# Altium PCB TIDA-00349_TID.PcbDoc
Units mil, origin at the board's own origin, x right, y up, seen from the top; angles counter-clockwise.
Board outline 2200 x 1000 mil, 2 copper layers (Top Layer, Bottom Layer), stack 62 mil thick; 48 components, 20 nets, 93 pads, 4 vias.
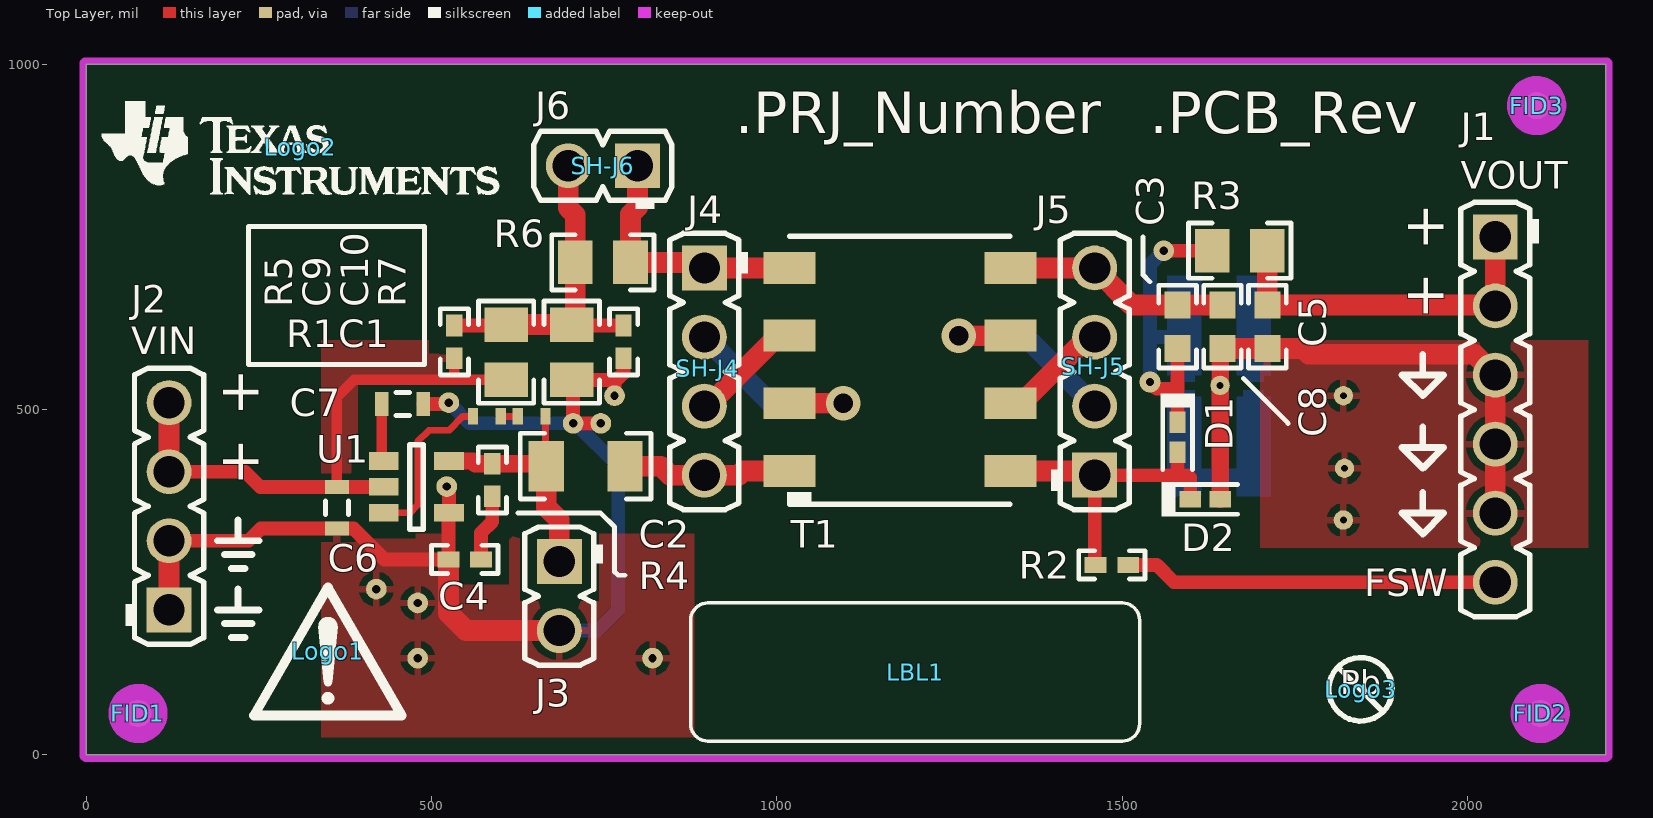
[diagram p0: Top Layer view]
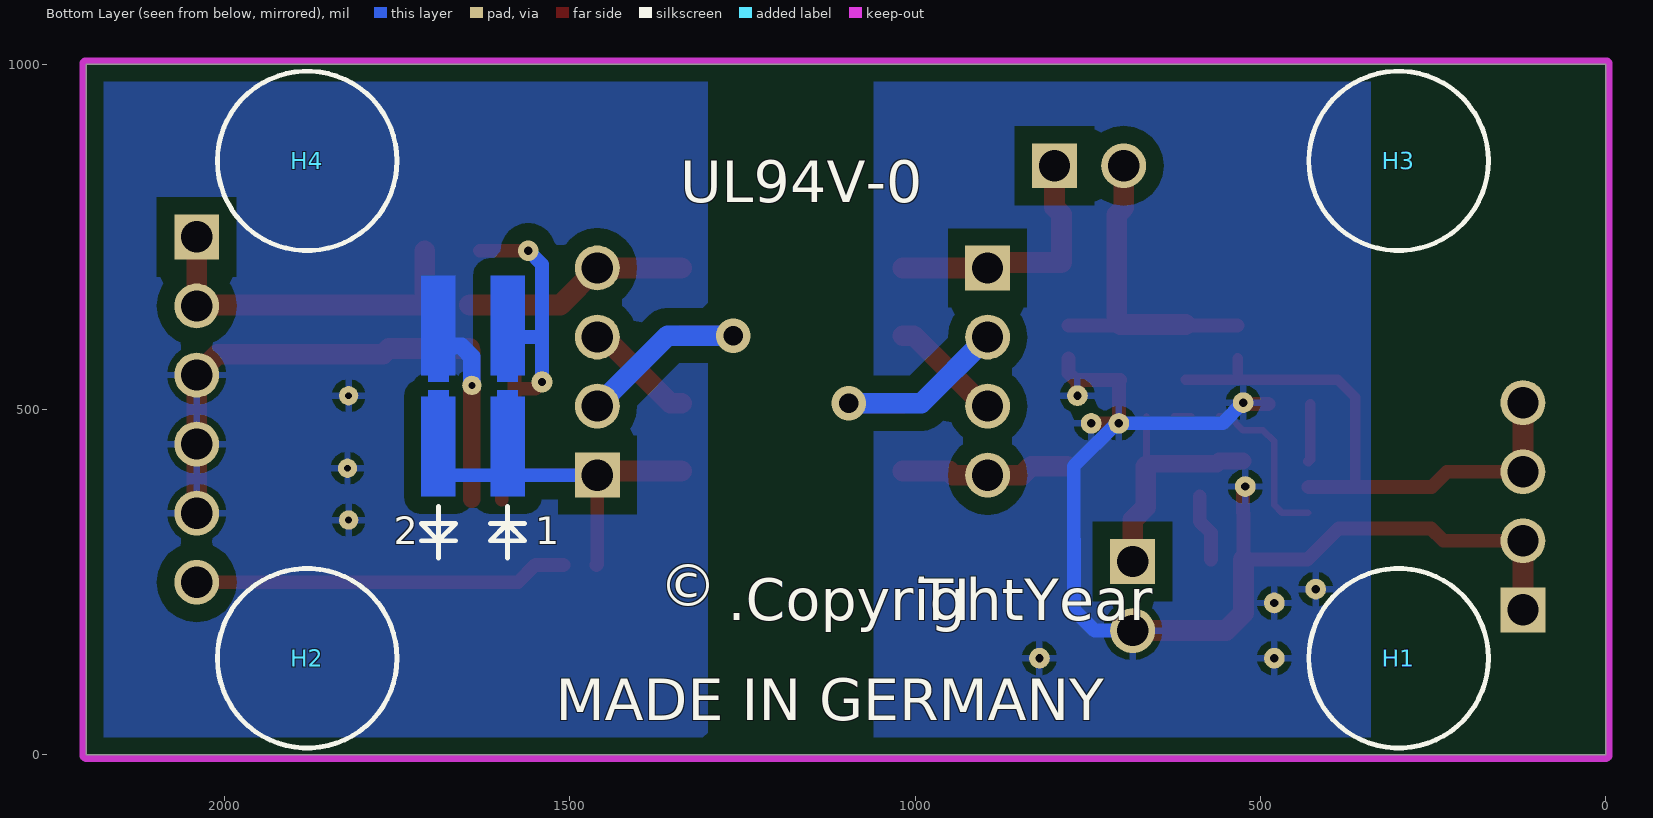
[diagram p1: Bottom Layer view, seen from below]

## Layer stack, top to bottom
Top Solder: solder mask 0.4, Solder Resist, Dk 3.5
Top Layer: signal copper 1.4
Dielectric1: core 59.2, FR-4, Dk 4.8
Bottom Layer: signal copper 1.4
Bottom Solder: solder mask 0.4, Solder Resist, Dk 3.5

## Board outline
0,0 2200,0 2200,1000 0,1000

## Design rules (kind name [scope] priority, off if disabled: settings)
AcuteAngle [All] p1: minimum=4.50000000000000E+0001 checktracksonly=FALSE
AssemblyTestPointUsage [All] p1: valid=2
Clearance Clearance_Keepouts [((IsTrack Or IsArc) And Not InPoly) And IsFree and IsKeepOut vs ((IsTrack Or IsArc) And Not InPoly) And IsFree and IsKeepOut] p1: gap=0
Clearance Clearance_BoardEdge_MountingHoles [OnCopper and InComponentClass('Mounting Holes') vs IsKeepOut] p2: gap=40
Clearance Clearance_BoardEdge_Poly [OnCopper and InPoly vs IsKeepOut] p3: gap=25
Clearance Clearance_BoardEdge [OnCopper and Not InComponentClass('Logo') and not InComponentClass('FiducialMark') and not InRegion(1000,500,4000,800) and Not IsKeepout vs IsKeepOut] p4: gap=75
Clearance Clearance_Poly [InPolygon] p5: gap=25
Clearance [All] p6: gap=7.87
ComponentClearance ComponentClearance_MountingHoles_FiducialMarks [InComponentClass('Mounting Holes') vs InComponentClass('FiducialMark')] p1: gap=50 collisioncheckmode=3 verticalgap=10 showdistances=FALSE
ComponentClearance ComponentClearance_Shunt [InComponentClass('Header') vs InComponentClass('Shunt')] p2: gap=0 collisioncheckmode=3 verticalgap=0 showdistances=FALSE
ComponentClearance ComponentClearance_Logo [InComponentClass('Logo')] p3: gap=50 collisioncheckmode=3 verticalgap=10 showdistances=FALSE
ComponentClearance ComponentClearance_ScrewToNut [(HasFootprint('NY PMS 440 0025 PH')) vs (HasFootprint('Keystone_1902C'))] p4: gap=5 collisioncheckmode=3 verticalgap=10 showdistances=FALSE
ComponentClearance ComponentClearance_MountingHoles [InComponentClass('Mounting Holes')] p5: gap=250 collisioncheckmode=3 verticalgap=100000 showdistances=FALSE
ComponentClearance ComponentClearance_SmallPassives [HasFootprint('0201*') or HasFootprint('0402*') or HasFootprint('0508') or HasFootprint('0603*') or HasFootprint('0612') or HasFootprint('0805*') or HasFootprint('0815*') or HasFootprint('0830*') or HasFootprint('1206*') or HasFootprint('1210*') or HasFootprint('1808*') or HasFootprint('1812*') or HasFootprint('1825*') or HasFootprint('2010*') or HasFootprint('2220*') or HasFootprint('2225*') or HasFootprint('2512*') or HasFootprint('2728*') or HasFootprint('3518*') vs HasFootprint('0201*') or HasFootprint('0402*') or HasFootprint('0508') or HasFootprint('0603*') or HasFootprint('0612') or HasFootprint('0805*') or HasFootprint('0815*') or HasFootprint('0830*') or HasFootprint('1206*') or HasFootprint('1210*') or HasFootprint('1808*') or HasFootprint('1812*') or HasFootprint('1825*') or HasFootprint('2010*') or HasFootprint('2220*') or HasFootprint('2225*') or HasFootprint('2512*') or HasFootprint('2728*') or HasFootprint('3518*')] p6: gap=20 collisioncheckmode=3 verticalgap=10 showdistances=FALSE
ComponentClearance ComponentClearance_THtoSMT [IsThruComponent vs IsSMTComponent] p7: gap=50 collisioncheckmode=3 verticalgap=30 showdistances=FALSE
ComponentClearance ComponentClearance_THtoTH [IsThruComponent vs IsThruComponent] p8: gap=50 collisioncheckmode=3 verticalgap=30 showdistances=FALSE
ComponentClearance [All] p9: gap=40 collisioncheckmode=3 verticalgap=10 showdistances=FALSE
DiffPairsRouting [All] p1: maxlimit=100 minlimit=10 mostfreqgap=10 toplayer_minwidth=15 toplayer_maxwidth=15 toplayer_prefwidth=15 bottomlayer_minwidth=15 bottomlayer_maxwidth=15 bottomlayer_prefwidth=15 maxuncoupledlength=1000
FabricationTestPointUsage TestPointUsage [All] p1: valid=2 allowmultiple=FALSE
FabricationTestpoint Testpoint [All] p1: side=3 testpointundercomponent=TRUE minsize=40 maxsize=100 preferedsize=60 minholesize=0 maxholesize=40 preferedholesize=32 testpointgrid=1 allowsidetop=TRUE allowsidebottom=TRUE usegrid=TRUE gridtolerance=0.01
FanoutControl Fanout_LCC [IsLCC] p1: bgadir=Out bgaviamode=Centered fanoutstyle=Auto fanoutdirection=Alternating viagrid=1 // Fanout_LCC (Default Rule)
FanoutControl Fanout_BGA [IsBGA] p2: bgadir=Out bgaviamode=Centered fanoutstyle=Auto fanoutdirection=Alternating viagrid=1 // Fanout_BGA (Default Rule)
FanoutControl Fanout_Default [All] p4: bgadir=Out bgaviamode=Centered fanoutstyle=Auto fanoutdirection=Alternating viagrid=1 // Fanout_Default (Default Rule)
FanoutControl Fanout_Small [(CompPinCount < 5)] p5: bgadir=Out bgaviamode=Centered fanoutstyle=Auto fanoutdirection=OutThenIn viagrid=1 // Fanout_Small (Default Rule)
HoleSize [All] p1: absolutevalues=TRUE maxlimit=251 minlimit=8 maxpercent=80.000 minpercent=20.000
MinimumAnnularRing MinimumAnnularRing_ThermalPadVias [IsVia and InAnyComponent] p1: minimumring=5.91
MinimumAnnularRing [All] p2: minimumring=9
MinimumSolderMaskSliver MinimumSolderMaskSliver_Logo [InComponentClass('Logo') vs InComponentClass('Logo')] p1: minsoldermaskwidth=0.7
MinimumSolderMaskSliver [All] p2: minsoldermaskwidth=3.94
PlaneConnect [All] p1: planeconnectstyle=Relief reliefexpansion=10 reliefentries=4 reliefconductorwidth=10 reliefairgap=10
PolygonConnect [All] p1: connectstyle=Relief reliefconductorwidth=10 reliefentries=4 polygonreliefangle="90 Angle" airgapwidth=10
RoutingVias ThermalPadVias [IsVia and InAnyComponent] p1: holewidth=7.87 width=19.68 viastyle="Through Hole" minholewidth=7.87 minwidth=19.68 maxholewidth=12.99 maxwidth=23.62
RoutingVias [All] p2: holewidth=16 width=34 viastyle="Through Hole" minholewidth=7.87 minwidth=26 maxholewidth=40 maxwidth=65
SilkToBoardRegionClearance [Not ((IsComment or IsDesignator) And (Hide <> 'False')) and not InRegion(1000,500,4000,800)] p1:
SilkToSilkClearance SilkToSilkClearance_Pb-FreeLogo [(HasFootprint('Pb-Free_Overlay_Medium') OR HasFootprint('Pb-Free_Overlay_Small')) vs (HasFootprint('Pb-Free_Overlay_Medium') OR HasFootprint('Pb-Free_Overlay_Small'))] p1: silktosilkclearance=0
SilkToSilkClearance [All] p2: silktosilkclearance=5
SilkToSolderMaskClearance "Silk to Solder Mask Opening" [All] p1: minsilkscreentomaskgap=1 clearancetoexposedcopper=FALSE
SolderMaskExpansion [All] p1: expansion=1.97
UnpouredPolygon [All] p1: allowunpoured=FALSE
Width [All] p1: maxlimit=100 minlimit=6 preferedwidth=10 checkconnectedcopper=TRUE
14 further rules are at their usual default settings.

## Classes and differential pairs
component class TIDA-00349_TID_Hardware: !PCB1 FID1 FID2 FID3 H1 H2 H3 H4 LBL1 Logo1 Logo2 Logo3 ZZ1 ZZ2 ZZ3 ZZ4 ZZ5 ZZ6 ZZ7
component class TIDA-00349_IsolatedDCDC: C1 C2 C3 C4 C5 C6 C7 C8 C9 C10 D1 D2 J1 J2 J3 J4 J5 J6 R1 R2 R3 R4 R5 R6 R7 SH-J4 SH-J5 SH-J6 T1 U1
component class Shunt: SH-J4 SH-J5 SH-J6
component class Header: J1 J2 J3 J4 J5 J6
component class FiducialMark: FID1 FID2 FID3
component class Logo: Logo2
component class AssemblyNote: ZZ1 ZZ2 ZZ3 ZZ4 ZZ5 ZZ6 ZZ7
component class Label: LBL1

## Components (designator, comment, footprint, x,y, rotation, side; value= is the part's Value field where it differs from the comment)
C1 "CAP, CERM, 1uF, 10V, +/-10%, X5R, 0402" 0402S 645,490 r0 top
C2 "CAP, CERM, 22uF, 10V, +/-10%, X5R, 1206" 1206 723.01,418 r180 top
C3 "CGB3B1X5R1A475K055AC" 0603 1580,620 r90 top
C4 "GRM155R71H561KA01D" 0402 548.01,283 r180 top
C5 "C1608X5R1E685K080AC" 0603 1710,620 r270 top
C6 "C0603C475K8PACTU" 0603S 363.01,358 r270 top
C7 "GRM188R71A105KA61D" 0603S 458.01,508 r0 top
C8 "CGB3B1X5R1A475K055AC" 0603 1645,620 r270 top
C9 "CAP, CERM, 10uF, 10V, +/-10%, X7R, 0805" 0805_HV 608.01,583 r90 top
C10 "CAP, CERM, 10uF, 10V, +/-10%, X7R, 0805" 0805_HV 703.01,583 r270 top
D1 "RB520S30,115" SOD-523 1580,460 r270 top
D2 "RB520S30,115" SOD-523 1620,370 r0 top
FID1 "Fiducial" Fiducial10-20 75,60 r0 top
FID2 "Fiducial" Fiducial10-20 2105,60 r0 top
FID3 "Fiducial" Fiducial10-20 2100,940 r0 top
H1 "SJ5382" 3M_SJ5382 300,140 r180 bottom
H2 "SJ5382" 3M_SJ5382 1880,140 r180 bottom
H3 "SJ5382" 3M_SJ5382 300,860 r180 bottom
H4 "SJ5382" 3M_SJ5382 1880,860 r180 bottom
J1 "61300611121" WURTH_61300611121 2040,500 r270 top
J2 "61300411121" WURTH_61300411121 120,360 r90 top
J3 "61300211121" WURTH_61300211121 685,230 r270 top
J4 "61300411121" WURTH_61300411121 895,555 r270 top
J5 "61300411121" WURTH_61300411121 1460,555 r90 top
J6 "61300211121" WURTH_61300211121 748.02,853 r180 top
LBL1 "Size: 0.65\" x 0.20 \"" Label_650x200 1200,120 r0 top
Logo1 "CAUTION.  READ USER GUIDE BEFORE USE" IEC_Caution_Small 350,150 r0 top
Logo2 "Texas Instruments" TI_Stacked_Overlay_Small_Vertical 310,880 r270 top
Logo3 "Pb-Free Symbol" Pb-Free_Overlay_Small 1845,95 r0 top
R1 "RES, 1.00k ohm, 1%, 0.063W, 0402" 0402S 580,490 r0 top
R2 "CRCW040210K0FKED" 0402 1485,275 r0 top
R3 "CRCW08050000Z0EAHP" 0805_HV 1670,730 r0 top
R4 "RES, 10.0 ohm, 1%, 0.063W, 0402" 0402 588.01,398 r90 top
R5 "RES, 499k ohm, 1%, 0.063W, 0402" 0402 533.01,598 r270 top
R6 "CRCW08050000Z0EAHP" 0805_HV 748.01,713 r180 top
R7 "RES, 499k ohm, 1%, 0.063W, 0402" 0402 778.01,598 r90 top
SH-J4 "969102-0000-DA" SNT-100-BK-G 900,560 r90 top
SH-J5 "969102-0000-DA" SNT-100-BK-G 1458.01,563 r90 top
SH-J6 "969102-0000-DA" SNT-100-BK-G 748.01,853 r180 top
T1 "750314839" Wurth_750314445 1178.01,558 r90 top
U1 "TPS60402DBV" DBV0005A_N 478.01,388 r0 top
ZZ1 "These assemblies are ESD sensitive, ESD precautions shall be observed." AssemblyNote 150,1975 r0 top
ZZ2 "These assemblies must be clean and free from flux and all contaminants. Use of no clean flux is not acceptable." AssemblyNote 150,1850 r0 top
ZZ3 "This Assembly Note is for PCB labels only" AssemblyNoteLabel 150,1725 r0 top
ZZ4 "These assemblies must comply with workmanship standards IPC-A-610 Class 2, unless otherwise specified." AssemblyNote 150,1600 r0 top
ZZ5 "Jumper/Shunt: SH-J4 on J4-PINs 2-3" AssemblyNote 150,1475 r0 top
ZZ6 "Jumper/Shunt: SH-J5 on J5-PINs 2-3" AssemblyNote 150,1350 r0 top
ZZ7 "Jumper/Shunt: SH-J6 on J6-PINs 1-2" AssemblyNote 150,1225 r0 top

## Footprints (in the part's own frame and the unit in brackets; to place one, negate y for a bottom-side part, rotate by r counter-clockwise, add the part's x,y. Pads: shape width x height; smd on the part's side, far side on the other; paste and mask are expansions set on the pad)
3M_SJ5382 [mil] "3M BUMPON"
  silkscreen extent -130,-130 130,130, body extent -124,-125 125,125, height 73
0402 [mm] "0402 from SM-752 data"
  rect 0.8x0.6 smd: 1(-0.6,0) 2(0.6,0)
  silkscreen extent -1.22,-0.52 1.22,0.52, body extent -0.55,-0.3 0.55,0.3, height 0.6
0402S [mil] "Based on C0402S footprint from PADS legacy"
  rect 15x24 smd: 1(-20,0) 2(20,0)
  body extent -22,-12 22,12, height 24
0603 [mm] "0603 from SM-752 data"
  rect 1x0.95 smd: 1(-0.8,0) 2(0.8,0)
  silkscreen extent -1.52,-0.69 1.52,0.69, body extent -0.87,-0.47 0.87,0.47, height 0.85
0603S [mil]
  rect 20x35 smd: 1(-30,0) 2(30,0)
  silkscreen extent -10,-17 10,17, body extent -34,-19 34,19, height 33
0805_HV [mil] "0805 with 30mil clearance between pads"
  rect 50x63 smd: 1(-40,0) 2(40,0)
  silkscreen extent -74,-40 74,40, body extent -43,-29 43,29, height 43
1206 [mm] "1206 from SM-752 data"
  rect 1.3x1.85 smd: 1(-1.45,0) 2(1.45,0)
  silkscreen extent -2.4,-1.21 2.4,1.21, body extent -1.7,-0.9 1.7,0.9, height 1.35
AssemblyNote [mil] "Assembly Note"
AssemblyNoteLabel [mil] "Assembly Note for PCB Labels"
DBV0005A_N [mm] "SOT23, 5-Leads, Body 2.9x1.6mm, Pitch 0.95mm, Lead Span 2.8mm, IPC Medium Density"
  rect 1.1x0.65 smd: 1(-1.2,0.95) 2(-1.2,0) 3(-1.2,-0.95) 4(1.2,-0.95) 5(1.2,0.95)
  silkscreen extent -0.25,-1.55 0.25,1.55, body extent -1.42,-1.46 1.42,1.46, height 1.08
Fiducial10-20 [mm]
  round 1 smd mask+0.5: 1(0,0)
  Top Layer keep-out circle w1.178: c0,0 r0.5
IEC_Caution_Small [mil]
  silkscreen extent -107,-93 107,92
Label_650x200 [mil] "Thermal Transfer Label"
  round 1 on Mech13: 0(0,0)
  silkscreen extent -325,-100 325,100, body extent -326,-101 326,101, height 1
Pb-Free_Overlay_Small [mil]
  silkscreen extent -46,-46 46,46
SNT-100-BK-G [mil] "Samtec STEP model"
  round 1 on Mech3: 0(0,0)
  body extent -100,-50 100,50, height 344
SOD-523 [mm] "NXP Semiconductor recommended land pattern, nominal STEP model"
  rect 0.8x0.6 smd paste-0.05: 1(-0.55,0) 2(0.55,0)
  silkscreen extent -1.6,-0.64 1.2,0.63, body extent -0.8,-0.4 0.8,0.4, height 0.72
TI_Stacked_Overlay_Small_Vertical [mil]
  silkscreen extent -66,-288 69,288
Wurth_750314445 [mm] "WURTH"
  rect 1.17x1.91 smd: 1(-3.735,4.065) 2(-1.245,4.065) 3(1.245,4.065) 4(3.735,4.065) 5(3.735,-4.065) 6(1.245,-4.065) 7(-1.245,-4.065) 8(-3.735,-4.065)
  silkscreen extent -5,-4.05 4.9,4.15, body extent -4.92,-4.58 4.9,4.58, height 10.1
WURTH_61300211121 [mm] "Header, 2.54mm, 2x1, TH"
  rect 1.65x1.65 hole 1.15: 1(-1.27,0)
  round 1.65 hole 1.15: 2(1.27,0)
  silkscreen extent -2.54,-1.27 2.54,1.6, body extent -2.54,-1.27 2.54,1.27, height 8.54
WURTH_61300411121 [mm] "Header, 2.54mm, 4x1, TH"
  rect 1.65x1.65 hole 1.15: 1(-3.81,0)
  round 1.65 hole 1.15: 2(-1.27,0) 3(1.27,0) 4(3.81,0)
  silkscreen extent -5.08,-1.27 5.08,1.6, body extent -5.08,-1.27 5.08,1.27, height 8.54
WURTH_61300611121 [mm] "Header, 2.54mm, 6x1, TH"
  rect 1.65x1.65 hole 1.15: 1(-6.35,0)
  round 1.65 hole 1.15: 2(-3.81,0) 3(-1.27,0) 4(1.27,0) 5(3.81,0) 6(6.35,0)
  silkscreen extent -7.62,-1.27 7.62,1.6, body extent -7.62,-1.27 7.62,1.27, height 8.54

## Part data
C1: library part GRM155R61A105KE15D
C2: library part GRM31CR61A226KE19L
C3 C8: "CAP, CERM, 4.7 µF, 10 V, +/- 10%, X5R, 0603"
C4: "CAP, CERM, 560pF, 50V, +/-10%, X7R, 0402"
C5: "CAP, CERM, 6.8 µF, 25 V, +/- 10%, X5R, 0603"
C6: "CAP, CERM, 4.7uF, 10V, +/-10%, X5R, 0603"
C7: "CAP, CERM, 1uF, 10V, +/-10%, X7R, 0603"
C9 C10: library part GRM21BR71A106KE51L
D1 D2: "Diode, Schottky, 30 V, 0.2 A, SOD-523"
FID1 FID2 FID3: "Fiducial mark.  There is nothing to buy or mount."
H1 H2 H3 H4: "Bumpon, Hemisphere, 0.25 X 0.075, Clear"
J1: "Header, 2.54 mm, 6x1, Gold, TH"
J2 J4 J5: "Header, 2.54 mm, 4x1, Gold, TH"
J3 J6: "Header, 2.54 mm, 2x1, Gold, TH"
LBL1: library part THT-14-423-10, "Thermal Transfer Printable Labels, 0.650\" W x 0.200\" H - 10,000 per roll"
Logo1: library part IEC_Caution, "IEC 61010-1 Caution Warning"
Logo2: library part TI_Logo, "Texas Instrument Corporate Signature"
Logo3: library part Pb-Free
R1: library part CRCW04021K00FKED
R2: "RES, 10.0 k, 1%, 0.063 W, 0402"
R3 R6: "RES, 0, 5%, 0.333 W, 0805"
R4: library part CRCW040210R0FKED
R5 R7: library part CRCW0402499KFKED
SH-J4 SH-J5 SH-J6: "Shunt, 100mil, Gold plated, Black"
T1: "Transformer, 3mH, SMT"
U1: "UNREGULATED 60-mA CHARGE PUMP VOLTAGE INVERTER, DBV0005A"
ZZ1 ZZ2 ZZ4 ZZ5 ZZ6 ZZ7: library part AssemblyNote
ZZ3: library part AssemblyNoteLabel

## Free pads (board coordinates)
  round 30 hole 12: 0(420,240) 0(480,140) 0(480,220) 0(522,388.55) 0(525,510) 0(705,480) 0(745,480) 0(765,520) 0(820,140)
  round 28 hole 10: 0(1641.65,535) 0(1820,340) 0(1820,520) 0(1821.65,415)

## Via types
v1: diameter 30, hole 12, Top Layer to Bottom Layer, 2 vias
v2: diameter 50, hole 28, Top Layer to Bottom Layer, 2 vias

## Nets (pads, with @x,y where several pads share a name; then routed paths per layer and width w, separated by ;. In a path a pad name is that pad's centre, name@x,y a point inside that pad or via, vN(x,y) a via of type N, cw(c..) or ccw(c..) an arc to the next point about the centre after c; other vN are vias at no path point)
GND: C4.2 C6.2 C7.2 C10.2 J2.1 J2.2 J3.2 pad.0@420,240 pad.0@480,140 pad.0@480,220 pad.0@522,388.55 pad.0@525,510 pad.0@705,480 pad.0@745,480 pad.0@765,520 pad.0@820,140 R7.1 U1.4 | length 1737.4
  Top Layer w20: J2.2 235,310 253,328 C6.2 387,328 432,283 C4.2 U1.4@524.39,349.73 ; C7.2 pad.0@523,508 ; pad.0@522,388.55 525.26,385.29 U1.4 ; pad.0@745,480 705,480 705,541.01 C10.2 768,543 ; pad.0@765,520 765,540 768,543 ; R7.1 778.01,553.01 768,543
  Top Layer w30: J2.1 J2.2 ; C4.2 524.39,205.61 550,180 J3.2
  Bottom Layer w20: pad.0@525,510 554.91,480.09 705,480 708.24,480 770.24,418 770,210 740,180 J3.2
ISOGND: C5.2 C8.2 D2.2 J1.3 J1.4 J1.5 pad.0@1641.65,535 pad.0@1820,340 pad.0@1820,520 pad.0@1821.65,415 | length 928.5
  Top Layer w25: D2.2 1641.65,535 1641.65,585.16 C8.2
  Top Layer w30: C8.2 C5.2 1761.5,588.5 1770,580 2010,580 J1.3 J1.4 J1.5
  Bottom Layer w25: pad.0@1641.65,535 1641.65,576.65 1656.95,591.95 1691.32,591.95
NetC1_1: C1.1 R1.2 | length 25
  Top Layer w10: R1.2 C1.1
NetC1_2: C1.2 C2.2 J3.1 R4.2 U1.5 | length 360.7
  Top Layer w10: C1.2 665,418.93 C2.2
  Top Layer w25: U1.5 559.6,425.4 563.38,421.62 R4.2 662.3,421.62 C2.2@665,418.93
  Top Layer w30: C2.2 665.93,359.07 685,340 J3.1
NetC2_1: C2.1 J4.4 T1.1 | length 245.7
  Top Layer w30: C2.1 832,418 845,405 J4.4 945,405 950.95,410.95 T1.1
NetC3_1: C3.1 D1.1 R3.1 | length 464.3
  Top Layer w20: v1(1540,540) 1550,530 1580,530 ; v1(1560,730) R3.1 ; D1.1 1580,530 ; C3.1 1580,530
  Bottom Layer w20: v1(1540,540) 1540,605 ; v1(1560,730) 1540,710 1540,605 ; 1585,605 1540,605
NetC3_2: C3.2 C8.1 J5.4 T1.5 | length 329.1
  Top Layer w30: T1.5 T1.5 J5.4 1513.5,651.5 C3.2 C8.1
NetC4_1: C4.1 R4.1 | length 98.2
  Top Layer w20: C4.1 571.63,321.63 588.01,338.01 R4.1
NetC5_1: C5.1 J1.1 J1.2 R3.2 | length 506.1
  Top Layer w30: R3.2 C5.1 2038.5,651.5 2040,652.99 J1.1
NetC7_1: C7.1 U1.1 | length 83.7
  Top Layer w15: C7.1 428.01,428.16 U1.1
NetC9_2: C9.2 C10.1 J6.2 R5.1 R6.2 R7.2 | length 482.4
  Top Layer w20: R5.1 606.63,621.62 C9.2 ; C10.1 704.39,621.62 R7.2
  Top Layer w30: C9.2 C10.1 708.01,628 R6.2 708.01,781.99 698.02,791.98 J6.2
NetD1_2: D1.2 D2.1 J5.1 R2.1 T1.8 | length 689.7
  Top Layer w20: R2.1 1460,276.38 J5.1 1580,405 ; D1.2 1580,405 ; D2.1 1598.35,401.65 1595,405 1580,405
  Top Layer w30: T1.8 1454.05,410.95 J5.1
  Bottom Layer w20: J5.1 1690,405
NetJ1_6: J1.6 R2.2 | length 541.7
  Top Layer w20: R2.2 1550,275 1575,250 J1.6
NetJ4_1: J4.1 J6.1 R6.1 T1.4 | length 377.4
  Top Layer w30: J6.1 798.02,792.77 788.01,782.77 R6.1 887,713 J4.1 1017.93,705 T1.4
NetJ4_2: J4.2 T1.2 | length 318.8
  Top Layer w30: T1.2 v2(1096.02,508.98)
  Bottom Layer w30: J4.2 991.02,508.98 v2(1096.02,508.98)
NetJ4_3: J4.3 T1.3 | length 165.2
  Top Layer w30: J4.3 900,505 1002.02,607.02 T1.3
NetJ5_2: J5.2 T1.6 | length 324.3
  Top Layer w20: J5.2@1468.01,508 J5.2@1468.01,518
  Top Layer w30: v2(1262.98,607.02) T1.6
  Bottom Layer w30: v2(1262.98,607.02) 1357.98,607.02 J5.2
NetJ5_3: J5.3 T1.7 | length 161.7
  Top Layer w30: T1.7 1354.14,508.98 1450.16,605 J5.3
NetR1_1: R1.1 U1.3 | length 240.9
  Top Layer w10: U1.3 468.77,350.6 480,361.83 480,453.87 496.13,470 525,470 545,490 R1.1
VIN: C6.1 C9.1 J2.3 J2.4 R5.2 U1.2 | length 837.9
  Top Layer w15: C6.1 363.01,518.01 388,543 530,543 ; R5.2 533.01,546.01 530,543 ; C9.1 530,543
  Top Layer w20: J2.3 230,410 252,388 C6.1 U1.2
  Top Layer w30: J2.3 J2.4
pads on no net: FID1.1 FID2.1 FID3.1 LBL1.0 SH-J4.0 SH-J5.0 SH-J6.0

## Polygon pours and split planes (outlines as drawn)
GND on Bottom Layer "Bottom Layer-No Net 1" (solid, remove dead copper, pour order 10): 340,0 340,1000 1060,1000 1060,0
ISOGND on Bottom Layer "Bottom Layer-No Net" (solid, remove dead copper, pour order 2): 2200,1000 1300,1000 1300,0 2200,0
ISOGND on Top Layer "Top Layer-No Net 2" (solid, remove dead copper, pour order 12): 1700,560 1700,300 2200,300 2200,600 1700,600
VIN on Top Layer "Top Layer-No Net 1" (solid, remove dead copper, pour order 8): 340,400 340,600 540,600 540,400
GND on Top Layer "Top Layer-No Net" (solid, remove dead copper, pour order 6): 340,320 340,0 880,0 880,320

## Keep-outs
Keep-Out Layer:
  lines w10: -5,0 ccw(c0,0) 0,-5 ; -5,0 ccw(c0,0) 0,-5 ; -5,0 -5,1000 ; -5,1000 cw(c0,1000) 0,1005 ; -5,1000 cw(c0,1000) 0,1005 ; 0,-5 2200,-5 ; 0,1005 2200,1005 ; 2200,-5 ccw(c2200,0) 2205,0 ; 2200,-5 ccw(c2200,0) 2205,0 ; 2200,1005 cw(c2200,1000) 2205,1000 ; 2200,1005 cw(c2200,1000) 2205,1000 ; 2205,0 2205,1000
  text ".Layer_Name" at 577,-858.49 h60

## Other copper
Top Layer:
  text ".Layer_Name" at 577,-858.49 h60
Bottom Layer:
  rectangle net NetC3_1: 1575,540 1605,549
  rectangle net NetD1_2: 1575,519 1605,528
  rectangle net NetD1_2: 1675,519 1705,528
  rectangle net ISOGND: 1675,540 1705,549
  rectangle net ISOGND: 1665,549 1715,694
  rectangle net NetD1_2: 1665,374 1715,519
  rectangle net NetD1_2: 1565,374 1615,519
  rectangle net NetC3_1: 1565,549 1615,694
  text ".Layer_Name" at 577,-858.49 h60

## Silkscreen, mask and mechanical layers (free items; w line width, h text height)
Top Overlay:
  lines w7: 625,350 745,350 765,330 765,265 770,260 780,260 ; 1530,750 1530,695 1540,685 ; 1675,545 1740,480 ; 235,565 235,765 490,765 490,565 235,565
  lines w10: 190,210 250,210 ; 190,310 250,310 ; 200,190 240,190 ; 200,290 240,290 ; 210,170 230,170 ; 210,270 230,270 ; 220,210 220,240 ; 220,310 220,340 ; 1935,350 1935,380 ; 1935,445 1935,475 ; 1935,550 1935,580 ; 1905,350 1965,350 1935,320 1905,350 ; 1905,445 1965,445 1935,415 1905,445 ; 1905,550 1935,520 1965,550 1905,550
  text ".PRJ_Number" at 940,900 h60
  text ".PCB_Rev" at 1540,900 h60
  text "VOUT" at 1990,820 h40
  text "+" at 1965,730 h60 r90
  text "+" at 1965,630 h60 r90
  text "VIN" at 65,580 h40
  text "+" at 250,490 h60 r90
  text "+" at 250,390 h60 r90
  text "FSW" at 1850,230 h40
  text ".Layer_Name" at 577,-858.49 h60
Bottom Overlay:
  lines w7: 1565,335 1615,335 ; 1590,285 1590,360 ; 1665,310 1715,310 ; 1690,285 1690,360 ; 1565,310 1590,335 1615,310 1565,310 ; 1665,335 1690,310 1715,335 1665,335
  text "UL94V-0" at 1340,800 h60
  text "1" at 1550,305 h40
  text "2" at 1755,305 h40
  text "TI" at 995,195 h60
  text ".CopyrightYear" at 1271,195 h60
  text "©" at 1370,195 h105
  text "MADE IN GERMANY" at 1520,50 h60
  text ".Layer_Name" at 577,-858.49 h60
Top Paste:
  text ".Layer_Name" at 577,-858.49 h60
Bottom Paste:
  text ".Layer_Name" at 577,-858.49 h60
Top Solder:
  text ".Layer_Name" at 577,-858.49 h60
  text ".Layer_Name" at 577,-858.49 h60
Bottom Solder:
  text ".Layer_Name" at 577,-858.49 h60
Drill Guide:
  text ".Layer_Name" at 577,-858.49 h60
M1 Board Outline:
  the board outline again, w10
  text ".Layer_Name" at 577,-858.49 h60
M2 Board Dimensions:
  rectangle: 125,-400 500,-275
  rectangle: 0,-275 125,-150
  lines w7: 0,-275 1000,-275 ; 125,-400 125,-150 ; 250,-400 250,-150 ; 500,-400 500,-150 ; 750,-400 750,-150 ; 0,-400 0,-150 1000,-150 1000,-400 0,-400
  text ".Layer_Name" at 577,-858.49 h60
M3 3D STEP Top:
  text ".Layer_Name" at 577,-858.49 h60
M4 3D STEP Bottom:
  text ".Layer_Name" at 577,-858.49 h60
M5 Assembly Top:
  lines w10: -292,-930.17 6308,-930.17 ; -292,-726.83 6310,-726.83 ; -292,-523.5 -292,-1133.5 3713,-1133.5 6310,-1133.5 6310,-523.5 -291.5,-523.5 -291.5,-1133.5 1284,-1133.5 ; 2173,-1133.5 2173,-523.5 ; 3440,-726.83 3440,-523.5 ; 4280,-726.83 4280,-523.5 ; 4902,-1140 4902,-937.17
  text "COMPONENTS MARKED 'DNP' SHOULD NOT BE POPULATED." at 1153.5,-318.5 h60
  text "ASSEMBLY VARIANT:" at 1153,-434 h60
  text ".VariantName" at 2189,-434 h60
  text "PCB VIEWED FROM TOP SIDE" at -228.5,-655.67 h60
  text "BOARD #:" at 2248,-655.67 h60
  text ".PRJ_Number" at 2793.5,-655.67 h60
  text "REV:" at 3638,-655.67 h60
  text ".PCB_Rev" at 3929.5,-655.67 h60
  text "SVN REV:" at 4476,-655.67 h60
  text ".VersionControl_RevNumber" at 4982,-655.67 h60
  text "PLOT NAME =" at -228.5,-1064.34 h60
  text ".plot_File_Name" at 577,-1064.34 h60
  text "GENERATED    :" at 2250,-1064.34 h60
  text ".Print_Date" at 3119.5,-1064.34 h60
  text ".Print_Time" at 3848.5,-1064.34 h60
  text "TEXAS INSTRUMENTS" at 5113,-1064.34 h60
M6 Assembly Bottom:
  lines w10: -292.5,-727.33 6309.5,-727.33 ; -290.5,-930.67 6309.5,-930.67 ; 1115.5,-1140.5 1115.5,-937.67 ; 1737.5,-727.33 1737.5,-524 ; 2577.5,-727.33 2577.5,-524 ; 3844.5,-1134 3844.5,-524 ; 4733.5,-1134 6309,-1134 6309,-524 -292.5,-524 -292.5,-1134 2304.5,-1134 6309.5,-1134 6309.5,-524
  text "COMPONENTS MARKED 'DNP' SHOULD NOT BE POPULATED." at 6102,-318 h60
  text ".VariantName" at 5058,-434 h60
  text "ASSEMBLY VARIANT:" at 6097,-434 h60
  text ".VersionControl_RevNumber" at 1035.5,-656.17 h60
  text "SVN REV:" at 1541.5,-656.17 h60
  text ".PCB_Rev" at 2088,-656.17 h60
  text "REV:" at 2379.5,-656.17 h60
  text ".PRJ_Number" at 3224,-656.17 h60
  text "BOARD #:" at 3769.5,-656.17 h60
  text "PCB VIEWED FROM BOTTOM SIDE" at 6246,-656.17 h60
  text "TEXAS INSTRUMENTS" at 904.5,-1064.84 h60
  text ".Print_Time" at 2169,-1064.84 h60
  text ".Print_Date" at 2898,-1064.84 h60
  text "GENERATED    :" at 3767.5,-1064.84 h60
  text ".plot_File_Name" at 5440.5,-1064.84 h60
  text "PLOT NAME =" at 6246,-1064.84 h60
M9 Title Sheet:
  drawing of 57 lines, arcs and shapes, not listed
  text "1" at 739.84,8036.5 h70
  text "2" at 3235.5,8036.5 h70
  text "3" at 5724.84,8036.5 h70
  text "4" at 8231.51,8036.5 h70
  text "5" at 10730.5,8036.5 h70
  text "6" at 13235.5,8036.5 h70
  text "A" at -416.5,6893.5 h70
  text "A" at 14383.5,6893.5 h70
  text "B" at -416.5,4513.5 h70
  text "B" at 14383.5,4513.5 h70
  text "C" at -416.5,2138.5 h70
  text "C" at 14383.5,2138.5 h70
  text "PROJECT TITLE:" at 11343.5,277.5 h45
  text ".PRJ_Title" at 11393.5,144.17 h70
  text "DESIGNED FOR:" at 11343.5,-23.5 h45
  text ".PRJ_Customer" at 11393.5,-163.5 h70
  text "D" at -416.5,-231.5 h70
  text "D" at 14383.5,-231.5 h70
  text "FILE NAME:" at 11343.5,-323.5 h45
  text ".PCB_File_Name_No_Path" at 11393.5,-443.5 h70
  text "Texas Instruments (TI) and/or its licensors do not warrant the accuracy or completeness of this specification" at 6374,-605.34 h45
  text "ENGINEER:" at 11343.5,-613.5 h45
  text "LAYOUT BY:" at 12848.5,-613.5 h45
  text "or any information contained therein. TI and/or its licensors do not warrant that this design will meet" at 6329.01,-718 h45
  text ".PRJ_Engineer" at 11393.5,-768.49 h70
  text ".PCB_Layout" at 12899,-768.49 h70
  text "the specifications, will be suitable for your application or fit for any particular purpose, or will operate in" at 6329.01,-830.67 h45
  text ".Layer_Name" at 577,-858.49 h60
  text "ALTIUM DESIGNER VERSION:" at 12848.5,-923.5 h45
  text "an implementation. TI and/or its licensors do not warrant that the design is production worthy. You should" at 6329.01,-943.33 h45
  text "completely validate and test your design implementation to confirm the system functionality for your application." at 6374,-1056 h45
  text ".print_Scale" at 11393.5,-1056.83 h70
  text ".Application_BuildNumber" at 12899,-1056.83 h70
  text "1" at 739.84,-1263.5 h70
  text "2" at 3235.5,-1263.5 h70
  text "3" at 5724.84,-1263.5 h70
  text "4" at 8231.51,-1263.5 h70
  text "5" at 10730.5,-1263.5 h70
  text "6" at 13235.5,-1263.5 h70
M10 Fab Notes:
  drawing of 185 lines, arcs and shapes, not listed
  text "DESIGN INFORMATION" at 12381.02,5910 h60
  text "MIN. TRACK WIDTH:" at 11736.46,5730 h60
  text "10" at 12832.7,5730 h60
  text "MIL" at 12987.46,5730 h60
  text "MIN. CLEARANCE:" at 11736.46,5598 h60
  text "0.2" at 12772.7,5598 h60
  text "mm" at 12987.46,5598 h60
  text "MIN. VIA PAD SIZE:" at 11736.46,5466 h60
  text "24" at 12802.71,5466 h60
  text "MIL" at 12987.46,5466 h60
  text "0.05mm (2MIL)" at 12431.46,5324.29 h60
  text "MINIMUM ANNULAR RING" at 11407.23,5320 h60
  text "EXTERNAL" at 13139.46,5320 h60
  text "PER" at 11607.23,5202 h60
  text "IPC-D-275 CLASS 2 LEVEL C" at 11827.23,5202 h60
  text "MIL, HOLES" at 13315.46,5089.71 h60
  text "+/-" at 12923,5089 h60
  text "+/-" at 13777,5089 h60
  text "REGISTRATION TOLERANCES:" at 11407.23,5084 h60
  text "METAL" at 12607,5084 h60
  text "5" at 13183.2,5084 h60
  text "3" at 14016.2,5084 h60
  text "MIL" at 14132.46,5084 h60
  text "MATERIAL:" at 11332.46,4874.54 h60
  text "FR-4 High Tg" at 12318.9,4734.21 h60
  text "FR-408" at 11753.46,4725.64 h60
  text "X" at 12165.46,4725.64 h60
  text "OTHER" at 13241.46,4725.64 h60
  text "62 MIL (1.6mm) +/-10%" at 12073.56,4562.92 h60
  text "THICKNESS:" at 11407.23,4558.64 h60
  text "X" at 11945.4,4558.64 h60
  text "OTHER" at 13358.46,4558.64 h60
  text "TOLERANCE:" at 11407.23,4400.64 h60
  text "X" at 12246.53,4400.64 h60
  text "ANSI IPC-6012 TYPE 3 CLASS 2" at 12433.48,4400.64 h60
  text "OTHER +/-" at 12433.46,4244.64 h60
  text "BOW & TWIST:" at 11407.23,4087.64 h60
  text "X" at 12246.53,4087.64 h60
  text "ANSI IPC-6012 TYPE 3 CLASS 2" at 12433.48,4087.64 h60
  text "OTHER +/-" at 12433.46,3929.13 h60
  text "DRILLING:" at 11332.46,3790.64 h60
  text "REFERENCE:" at 11407.23,3673.64 h60
  text "X" at 12055.46,3673.64 h60
  text "AS SHOWN" at 12242.46,3673.64 h60
  text "X" at 12956.46,3673.64 h60
  text "NC_DRILL FILES" at 13093.46,3673.64 h60
  text "PTH MIN COPPER THICKNESS:" at 11407.23,3515.64 h60
  text "X" at 12757.46,3515.64 h60
  text "1MIL" at 12894.46,3515.64 h60
  text "OTHER" at 13391.46,3515.64 h60
  text "BOARD FINISH:" at 11332.46,3356.64 h60
  text "SILKSCREEN:" at 11487.68,3238.64 h60
  text "X" at 12436.46,3238.64 h60
  text "TOP" at 12562.46,3238.64 h60
  text "X" at 12946.46,3238.64 h60
  text "BOTTOM" at 13073.46,3238.64 h60
  text "SILKSCREEN COLOR:" at 11487.68,3071.64 h60
  text "X" at 12435.42,3071.64 h60
  text "WHITE" at 12562.46,3071.64 h60
  text "OTHER" at 13073.46,3071.64 h60
  text "SOLDER RESIST COLOR:" at 11487.68,2901.64 h60
  text "X" at 12055.42,2742.44 h60
  text "GREEN" at 12182.46,2742.44 h60
  text "BLUE" at 12773.46,2742.44 h60
  text "OTHER" at 13311.46,2742.44 h60
  text "IMMERSION GOLD (ENIG)" at 12393.46,2553.92 h60
  text "ENEPIG" at 13731,2550.64 h60
  text "SURFACE FINISH:" at 11332.46,2549.64 h60
  text "X" at 12206.51,2549.64 h60
  text "IMM. TIN/SILVER OR EQUIV" at 11662,2392.64 h60
  text "OTHER" at 13093.46,2392.64 h60
  text "ARRAY/PANEL:" at 11332.46,2213.64 h60
  text "CUT AND TRIM PER MECH LAYER 1" at 12393.46,2209.35 h60
  text "N.C. ROUTE" at 12393.46,2057.64 h60
  text "X" at 13072.46,2057.64 h60
  text "V. SCORE" at 13259.46,2057.64 h60
  text "CERTIFICATION:" at 11332.46,1920.64 h60
  text "MATERIALS AND WORKMANSHIP FOR ALL PCBS" at 12057.46,1920.64 h60
  text "TO MEET OR EXCEED THE REQUIREMENTS OF:" at 12057.46,1822.64 h60
  text "X" at 11683.96,1686.13 h60
  text "ANSI IPC-A-600F CLASS ->" at 11822.96,1686.13 h60
  text "X" at 13462.02,1686.13 h60
  text "2" at 13580.96,1686.14 h60
  text "1" at 13265.96,1684.64 h60
  text "3" at 13934.96,1684.64 h60
  text "X" at 11686.02,1526.64 h60
  text "UL 94V-0" at 11822.96,1526.64 h60
  text "X" at 12498.02,1526.64 h60
  text "RoHS" at 12634.96,1526.64 h60
  text "OTHER" at 13279.36,1526.64 h60
  text "PER ORDER" at 13676.42,1526.64 h60
  text "ADDITIONAL REQUIREMENTS:" at 11332.46,1385.64 h60
  text "MICROSECTION:" at 11407.23,1270.64 h60
  text "YES" at 12312.96,1270.64 h60
  text "REQUIRED" at 13174.46,1114.49 h60
  text "BARE BOARD ELEC. TEST:" at 11407.23,1111.64 h60
  text "NONE" at 12712.96,1111.64 h60
  text "X" at 13047.46,1111.64 h60
  text "PER ORDER" at 13766.46,1111.64 h60
  text "MANUFACTURER'S UL:" at 11407.23,954.64 h60
  text "RAIL" at 12572.96,950.35 h60
  text "METAL" at 13064.77,950.35 h60
  text "X" at 13440,950 h60
  text "SILK" at 13576.46,950.35 h60
  text ".Layer_Name" at 577,-858.49 h60
M11 Gerber Information:
  lines w10: -292,-930.17 6308,-930.17 ; -292,-726.83 6310,-726.83 ; -292,-523.5 -292,-1133.5 3713,-1133.5 6310,-1133.5 6310,-523.5 -291.5,-523.5 -291.5,-1133.5 1284,-1133.5 ; 2173,-1133.5 2173,-523.5 ; 3440,-726.83 3440,-523.5 ; 4280,-726.83 4280,-523.5 ; 4902,-1140 4902,-937.17
  text "ALL ARTWORK VIEWED FROM TOP SIDE" at -228.5,-655.67 h60
  text "BOARD #:" at 2248,-655.67 h60
  text ".PRJ_Number" at 2793.5,-655.67 h60
  text "REV:" at 3638,-655.67 h60
  text ".PCB_Rev" at 3929.5,-655.67 h60
  text "SVN REV:" at 4476,-655.67 h60
  text ".VersionControl_RevNumber" at 4982,-655.67 h60
  text "LAYER NAME =" at -228.5,-858.49 h60
  text "PLOT NAME =" at -228.5,-1064.34 h60
  text ".plot_File_Name" at 577,-1064.34 h60
  text "GENERATED    :" at 2250,-1064.34 h60
  text ".Print_Date" at 3119.5,-1064.34 h60
  text ".Print_Time" at 3848.5,-1064.34 h60
  text "TEXAS INSTRUMENTS" at 5113,-1064.34 h60
M12 Stackup:
  drawing of 305 lines, arcs and shapes, not listed
  text "Layer" at 5150,7823.09 h60
  text "Name" at 5559.91,7823.09 h60
  text "Material" at 6489.66,7823.09 h60
  text "Thickness" at 7349.42,7823.09 h60
  text "Constant" at 7999.26,7823.09 h60
  text "Board Layer Stack" at 8569.12,7823.09 h60
  text "1" at 5150,7703.09 h60
  text "Top Overlay" at 5559.91,7703.09 h60
  text "2" at 5150,7583.09 h60
  text "Top Solder" at 5559.91,7583.09 h60
  text "Solder Resist" at 6489.66,7583.09 h60
  text "0.40mil" at 7349.42,7583.09 h60
  text "3.5" at 7999.26,7583.09 h60
  text "3" at 5150,7463.09 h60
  text "Top Layer" at 5559.91,7463.09 h60
  text "Copper" at 6489.66,7463.09 h60
  text "1.40mil" at 7349.42,7463.09 h60
  text "4" at 5150,7343.09 h60
  text "Dielectric1" at 5559.91,7343.09 h60
  text "FR-4" at 6489.66,7343.09 h60
  text "59.20mil" at 7349.42,7343.09 h60
  text "4.8" at 7999.26,7343.09 h60
  text "5" at 5150,7223.09 h60
  text "Bottom Layer" at 5559.91,7223.09 h60
  text "Copper" at 6489.66,7223.09 h60
  text "1.40mil" at 7349.42,7223.09 h60
  text "6" at 5150,7103.09 h60
  text "Bottom Solder" at 5559.91,7103.09 h60
  text "Solder Resist" at 6489.66,7103.09 h60
  text "0.40mil" at 7349.42,7103.09 h60
  text "3.5" at 7999.26,7103.09 h60
  text "7" at 5150,6983.09 h60
  text "Bottom Overlay" at 5559.91,6983.09 h60
  text ".Layer_Name" at 577,-858.49 h60
M13 Component Bodies Top:
  text ".Layer_Name" at 577,-858.49 h60
M14 Component Bodies Bottom:
  text ".Layer_Name" at 577,-858.49 h60
M15 Courtyards Top:
  text ".Layer_Name" at 577,-858.49 h60
M16 Courtyards Bottom:
  text ".Layer_Name" at 577,-858.49 h60
Drill Drawing:
  lines w1: 5547.84,1782.9 5597.62,1782.9 5572.73,1733.12 5547.84,1782.9 ; 5547.84,1882.46 5572.73,1894.9 5597.62,1882.46 5585.17,1907.35 5597.62,1932.24 5572.73,1919.79 5547.84,1932.24 5560.28,1907.35 5547.84,1882.46 ; 5547.84,2044.24 5560.28,2044.24 5572.73,2031.8 5585.17,2044.24 5597.62,2044.24 5585.17,2056.68 5597.62,2069.13 5585.17,2069.13 5572.73,2081.57 5560.28,2069.13 5547.84,2069.13 5560.28,2056.68 5547.84,2044.24 ; 5547.84,2181.13 5547.84,2193.57 5560.28,2206.02 5547.84,2218.46 5547.84,2230.91 5560.28,2230.91 5572.73,2218.46 5585.17,2230.91 5597.62,2230.91 5597.62,2218.46 5585.17,2206.02 5597.62,2193.57 5597.62,2181.13 5585.17,2181.13 5572.73,2193.57 5560.28,2181.13 5547.84,2181.13
  lines w12: 5480,1688.32 7596.94,1688.32 ; 5480,2285.66 7596.94,2285.66 ; 5850.25,1538.99 5850.25,2435 ; 6207.06,1538.99 6207.06,2435 ; 6868.16,1538.99 6868.16,2435 ; 7152.16,1538.99 7152.16,2435 ; 5480,1538.99 7596.94,1538.99 7596.94,2435 5480,2435 5480,1538.99
  text "Symbol" at 5569.6,2330.47 h72
  text "Quantity" at 5895.05,2330.47 h72
  text "Finished Hole Size" at 6251.86,2330.47 h72
  text "Plated" at 6912.96,2330.47 h72
  text "Hole Type" at 7196.96,2330.47 h72
  text "4" at 5895.05,2181.13 h60
  text "10.00mil (0.254mm)" at 6251.86,2181.13 h60
  text "PTH" at 6912.96,2181.13 h60
  text "Round" at 7196.96,2181.13 h60
  text "11" at 5895.05,2031.8 h60
  text "12.00mil (0.305mm)" at 6251.86,2031.8 h60
  text "PTH" at 6912.96,2031.8 h60
  text "Round" at 7196.96,2031.8 h60
  text "2" at 5895.05,1882.46 h60
  text "28.00mil (0.711mm)" at 6251.86,1882.46 h60
  text "PTH" at 6912.96,1882.46 h60
  text "Round" at 7196.96,1882.46 h60
  text "22" at 5895.05,1733.12 h60
  text "45.28mil (1.150mm)" at 6251.86,1733.12 h60
  text "PTH" at 6912.96,1733.12 h60
  text "Round" at 7196.96,1733.12 h60
  text "39 Total" at 5895.05,1583.79 h60
  text ".Layer_Name" at 577,-858.49 h60

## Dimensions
0,0 to 2200,0 on M2 Board Dimensions
0,0 to 0,1000 on M2 Board Dimensions
0,-400 to 1000,-400 on M2 Board Dimensions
